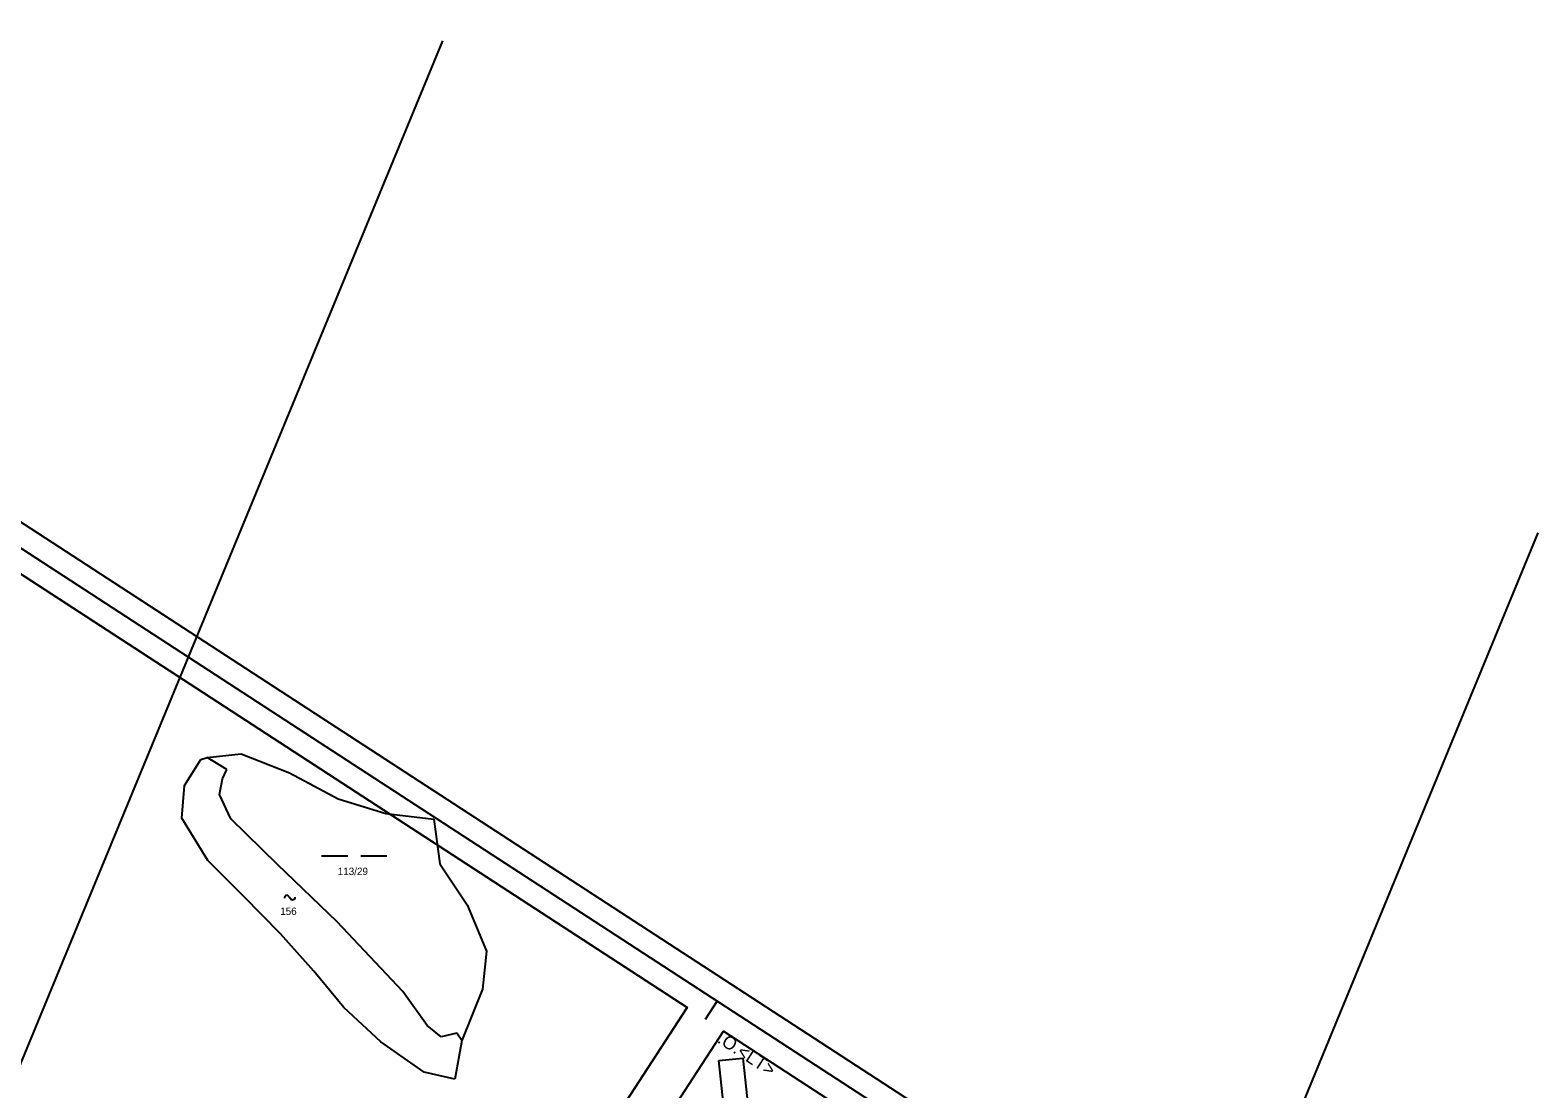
# Model space of a CAD drawing. Extents: x -866656 to -858817, y -1041816 to -1038653.
# Drawn here: x -861469.1 to -861122.1, y -1039644.9 to -1039401.3 of the extents above; entities that cross this region are included whole.
import ezdxf

# ---------------------------------------------------------------- set-up
doc = ezdxf.new("R2010")
doc.units = 0
for name, color, linetype in [('Hranice parcel', 7, 'Continuous'), ('Parcelní čísla', 7, 'Continuous'), ('tisk ramy', 7, 'Continuous'), ('Vrstva 21', 7, 'Continuous'), ('Značky budov', 7, 'Continuous'), ('Značky kultur', 7, 'Continuous')]:
    doc.layers.add(name, color=color, linetype=linetype)

msp = doc.modelspace()

# ---------------------------------------------------------------- linework, layer by layer
at = {"layer": 'Hranice parcel'}
for p, q in [((-861374.21, -1039403.71), (-861436.58, -1039554.81)), ((-861122.06, -1039516.99), (-861180.19, -1039657.84)), ((-861436.58, -1039554.81), (-861498.94, -1039705.92)), ((-861429.81, -1039569.14), (-861428.38, -1039568.62)), ((-861428.38, -1039568.62), (-861420.52, -1039567.78)), ((-861423.85, -1039571.39), (-861428.38, -1039568.62)), ((-861420.52, -1039567.78), (-861409.37, -1039572.17)), ((-861433.59, -1039575.06), (-861429.81, -1039569.14)), ((-861424.86, -1039573.53), (-861423.85, -1039571.39)), ((-861409.37, -1039572.17), (-861398.24, -1039578.19)), ((-861434.19, -1039582.64), (-861433.59, -1039575.06)), ((-861425.53, -1039577.17), (-861424.86, -1039573.53)), ((-861422.94, -1039582.75), (-861425.53, -1039577.17)), ((-861398.24, -1039578.19), (-861387.25, -1039581.54)), ((-861387.25, -1039581.54), (-861376.16, -1039582.85)), ((-861428.21, -1039592.35), (-861434.19, -1039582.64)), ((-861412.16, -1039593.29), (-861422.94, -1039582.75)), ((-861376.16, -1039582.85), (-861374.82, -1039593.1)), ((-861420, -1039600.57), (-861428.21, -1039592.35)), ((-861398.47, -1039606.44), (-861412.16, -1039593.29)), ((-861374.82, -1039593.1), (-861368.49, -1039602.52)), ((-861411.44, -1039609.19), (-861420, -1039600.57)), ((-861368.49, -1039602.52), (-861364.03, -1039613.2)), ((-861383.35, -1039622.49), (-861398.47, -1039606.44)), ((-861403.79, -1039617.85), (-861411.44, -1039609.19)), ((-861364.03, -1039613.2), (-861365, -1039621.92)), ((-861396.91, -1039626.15), (-861403.79, -1039617.85)), ((-861377.7, -1039630.35), (-861383.35, -1039622.49)), ((-861365, -1039621.92), (-861369.74, -1039633.75)), ((-861388.41, -1039634.06), (-861396.91, -1039626.15)), ((-861374.49, -1039632.94), (-861377.7, -1039630.35)), ((-861378.39, -1039641.08), (-861388.41, -1039634.06)), ((-861370.86, -1039632.11), (-861374.49, -1039632.94)), ((-861369.74, -1039633.75), (-861371.37, -1039642.66)), ((-861369.74, -1039633.75), (-861370.86, -1039632.11)), ((-861371.37, -1039642.66), (-861378.39, -1039641.08))]:
    msp.add_line(p, q, dxfattribs=at)
at = {"layer": 'tisk ramy'}
msp.add_line((-861313.67, -1039628.88), (-861310.95, -1039624.7), dxfattribs=at)
for points in [[(-862350.36, -1039297.02), (-861294.1, -1039983.97), (-861132.18, -1039735), (-862188.44, -1039048.05)], [(-862186.98, -1039054.97), (-861139.1, -1039736.46), (-861295.57, -1039977.05), (-862343.44, -1039295.55)], [(-862336.53, -1039294.09), (-861468.88, -1039858.37), (-861317.86, -1039626.16), (-862185.51, -1039061.88)], [(-862185.51, -1039061.88), (-861317.86, -1039626.16), (-861468.88, -1039858.37), (-862336.53, -1039294.09)]]:
    msp.add_lwpolyline(points, close=True, dxfattribs=at)
at = {"layer": 'Vrstva 21'}
for points in [[(-861342.79, -1039682.83), (-861309.48, -1039631.61), (-861208.89, -1039697.03), (-861242.2, -1039748.25)], [(-861310.59, -1039638.4), (-861305.04, -1039637.81), (-861302.83, -1039658.54), (-861308.38, -1039659.13)]]:
    msp.add_lwpolyline(points, close=True, dxfattribs=at)
at = {"layer": 'Značky budov'}
msp.add_line((-861409.49, -1039600.68), (-861409.19, -1039601.08), dxfattribs=at)
for centre, start, end in [((-861410, -1039600.97), 29.2914, 181.2189), ((-861408.68, -1039600.79), 209.2914, 1.2189)]:
    msp.add_arc(centre, 0.588, start, end, dxfattribs=at)
at = {"layer": 'Značky kultur'}
for p, q in [((-861402.01, -1039591.24), (-861396.01, -1039591.24)), ((-861393.01, -1039591.24), (-861387.01, -1039591.24))]:
    msp.add_line(p, q, dxfattribs=at)

# ---------------------------------------------------------------- texts
at = {"layer": 'Parcelní čísla'}
for s, p in [('113/29', (-861398.3, -1039595.7)), ('156', (-861411.54, -1039604.88))]:
    msp.add_text(s, height=1.7, dxfattribs=at).set_placement(p)
at = {"layer": 'tisk ramy'}
msp.add_text('.O.<LT>', height=3, rotation=326.9617, dxfattribs=at).set_placement((-861311.12, -1039634.12))

doc.saveas('drawing.dxf')
